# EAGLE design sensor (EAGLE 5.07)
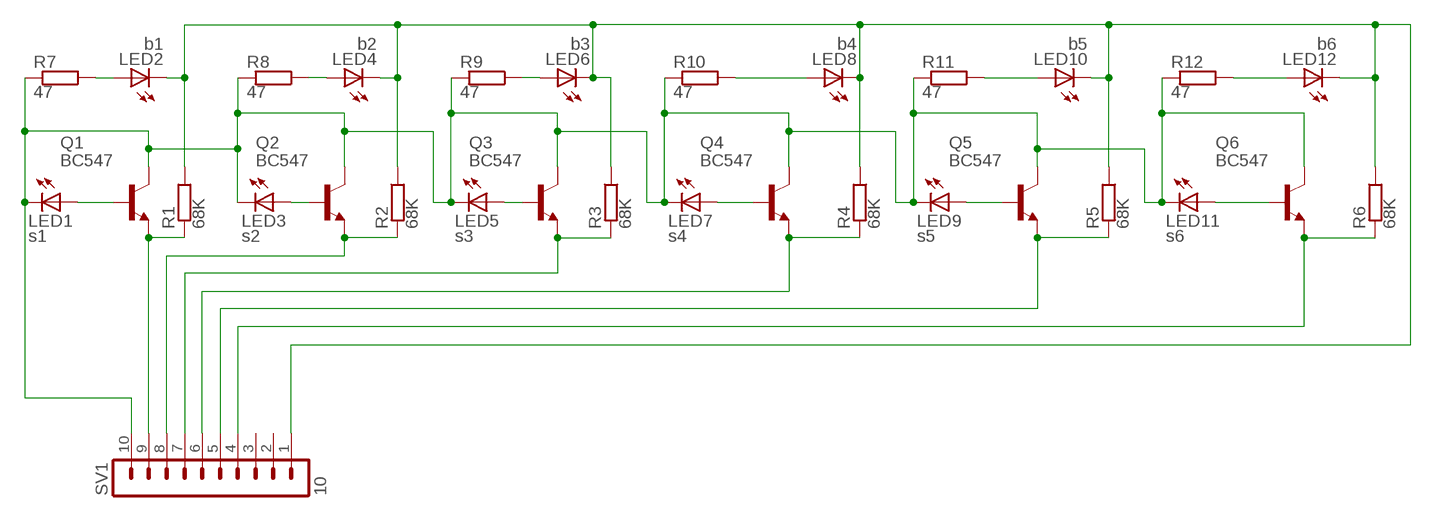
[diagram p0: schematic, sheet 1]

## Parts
LED1  s1  LED5MM  [LED5MM]
LED2  b1  LED5MM  [LED5MM]
LED3  s2  LED5MM  [LED5MM]
LED4  b2  LED5MM  [LED5MM]
LED5  s3  LED5MM  [LED5MM]
LED6  b3  LED5MM  [LED5MM]
LED7  s4  LED5MM  [LED5MM]
LED8  b4  LED5MM  [LED5MM]
LED9  s5  LED5MM  [LED5MM]
LED10  b5  LED5MM  [LED5MM]
LED11  s6  LED5MM  [LED5MM]
LED12  b6  LED5MM  [LED5MM]
Q1  BC547  [TO92]
Q2  BC547  [TO92]
Q3  BC547  [TO92]
Q4  BC547  [TO92]
Q5  BC547  [TO92]
Q6  BC547  [TO92]
R1  68K  SMK  [SMK]
R2  68K  SMK  [SMK]
R3  68K  SMK  [SMK]
R4  68K  SMK  [SMK]
R5  68K  SMK  [SMK]
R6  68K  SMK  [SMK]
R7  47  SMK  [SMK]
R8  47  SMK  [SMK]
R9  47  SMK  [SMK]
R10  47  SMK  [SMK]
R11  47  SMK  [SMK]
R12  47  SMK  [SMK]
SV1  10  MA10-1  [MA10-1]

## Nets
GRO: LED2.K(C) LED4.K(C) LED6.K(C) LED8.K(C) LED10.K(C) LED12.K(C) R1.1 R2.1 R3.1 R4.1 R5.1 R6.1 SV1.1
N$1: LED2.A R7.1
N$2: LED1.A Q1.2(B)
N$3: Q1.1(E) R1.2 SV1.9
N$4: LED4.A R8.1
N$5: LED6.A R9.1
N$6: LED3.A Q2.2(B)
N$7: Q2.1(E) R2.2 SV1.8
N$8: LED8.A R10.1
N$9: LED10.A R11.1
N$10: Q3.1(E) R3.2 SV1.7
N$11: LED5.A Q3.2(B)
N$12: LED12.A R12.1
N$14: LED9.A Q5.2(B)
N$17: Q5.1(E) R5.2 SV1.5
N$18: LED7.A Q4.2(B)
N$21: Q4.1(E) R4.2 SV1.6
N$23: LED11.A Q6.2(B)
N$24: Q6.1(E) R6.2 SV1.4
VCC: LED1.K(C) LED3.K(C) LED5.K(C) LED7.K(C) LED9.K(C) LED11.K(C) Q1.3(C) Q2.3(C) Q3.3(C) Q4.3(C) Q5.3(C) Q6.3(C) R7.2 R8.2 R9.2 R10.2 R11.2 R12.2 SV1.10
Unconnected: SV1.2 SV1.3

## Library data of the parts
LED1-LED12 = led:LED: LED
Q1-Q6 = transistor-npn:BC547*: NPN Transistor
R1-R12 = resistor-shunt:SMK: SMD SHUNT RESISTOR
SV1 = con-lstb:MA10-1: PIN HEADER

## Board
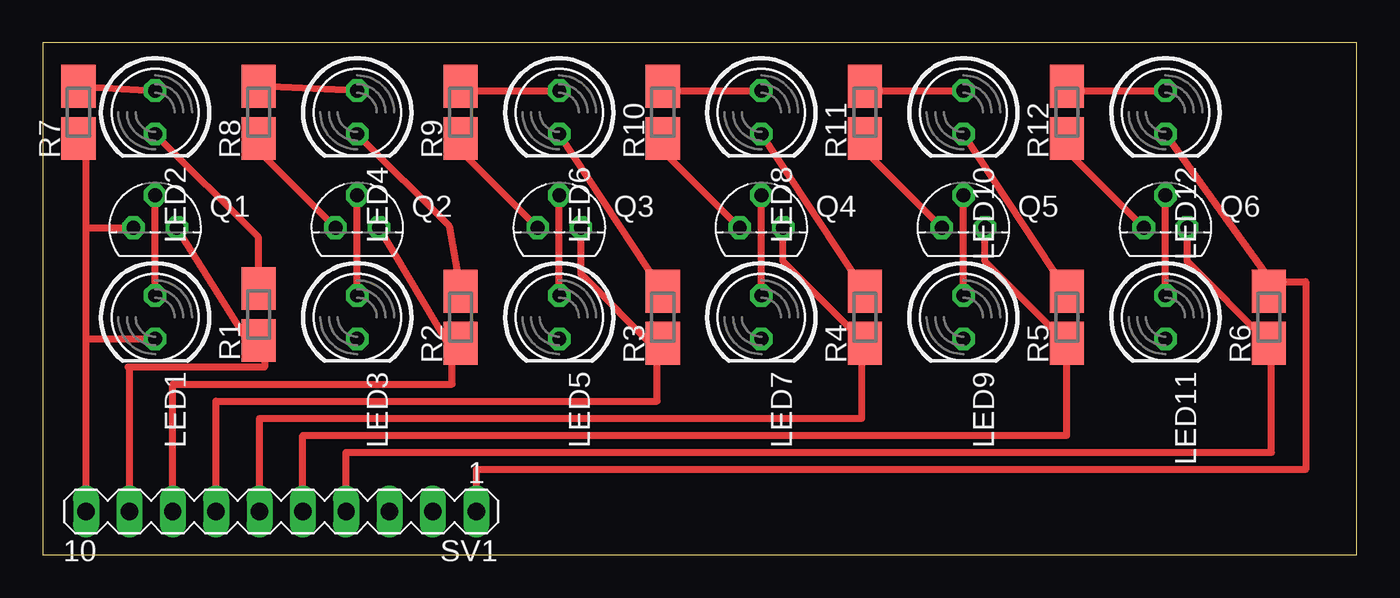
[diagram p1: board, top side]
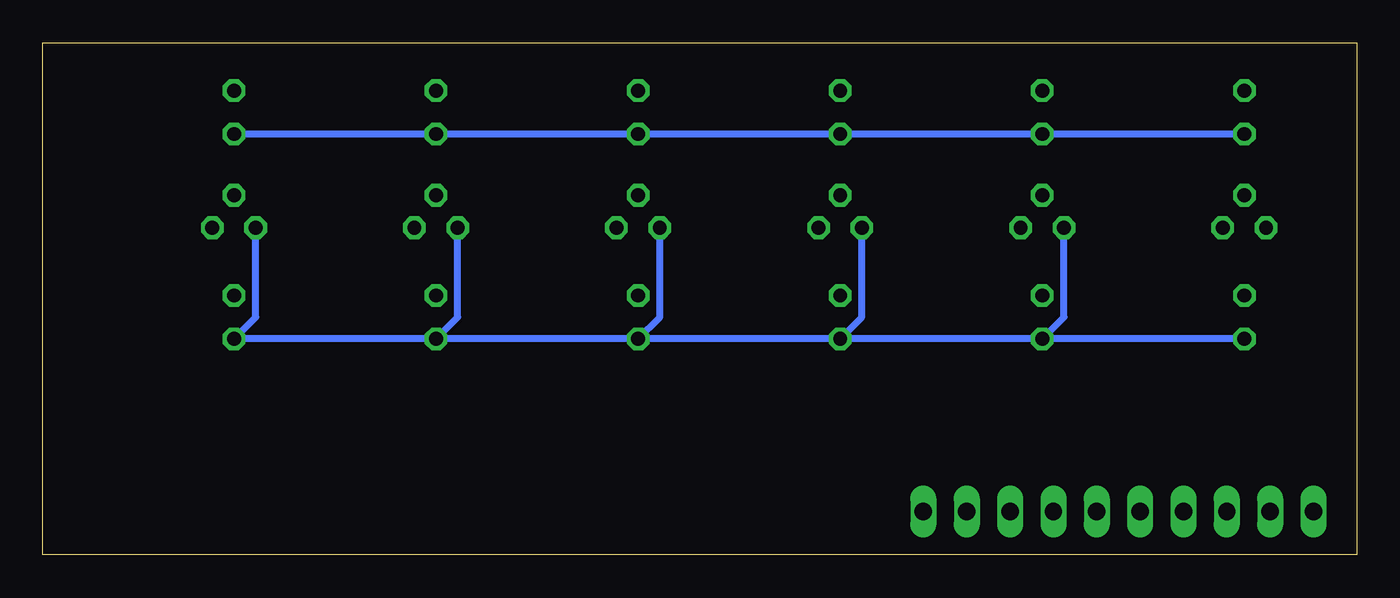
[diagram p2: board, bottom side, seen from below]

Size 77 x 30 mm. Coordinates in mm from the lower left corner, seen from the top.
Outline: 0,0 77,0 77,30 0,30 0,0
Copper layers (1*16): Top 0.035mm / dielectric 1.5mm / Bottom 0.035mm
Design rules "default": minimum track width 10mil, minimum drill 24mil, track to track 8mil, track to pad 8mil, pad to pad 8mil, via to via 8mil, smd to smd 8mil, copper to edge 40mil, drill to drill 8mil, minimum pad ring 10mil, minimum via ring 8mil, stop-mask expansion 4mil, vias tented up to drill 0mil, thermal gap 10mil

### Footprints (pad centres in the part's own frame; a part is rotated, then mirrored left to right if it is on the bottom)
LED5MM = drill 0.813 octagon: A -1.27,0; K 1.27,0
TO92 = drill 0.813 octagon: 1 1.27,0; 2 0,1.905; 3 -1.27,0
SMK = smd 2.5 x 2: 1 1.524,0; 2 -1.524,0
MA10-1 = drill 1.016 long: 1 -11.43,0; 2 -8.89,0; 3 -6.35,0; 4 -3.81,0; 5 -1.27,0; 6 1.27,0; 7 3.81,0; 8 6.35,0; 9 8.89,0; 10 11.43,0

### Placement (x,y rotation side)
LED1  6.59,13.92 270 top
LED2  6.59,25.92 270 top
LED3  18.43,13.92 270 top
LED4  18.43,25.92 270 top
LED5  30.27,13.92 270 top
LED6  30.27,25.92 270 top
LED7  42.11,13.92 270 top
LED8  42.11,25.92 270 top
LED9  53.95,13.92 270 top
LED10  53.95,25.92 270 top
LED11  65.79,13.92 270 top
LED12  65.79,25.92 270 top
Q1  6.59,19.16 0 top
Q2  18.43,19.16 0 top
Q3  30.27,19.16 0 top
Q4  42.11,19.16 0 top
Q5  53.95,19.16 0 top
Q6  65.79,19.16 0 top
R1  12.65,14.08 90 top
R2  24.49,13.92 90 top
R3  36.33,13.92 90 top
R4  48.17,13.92 90 top
R5  60.01,13.92 90 top
R6  71.85,13.92 90 top
R7  2.1,25.92 90 top
R8  12.65,25.92 90 top
R9  24.49,25.92 90 top
R10  36.33,25.92 90 top
R11  48.17,25.92 90 top
R12  60.01,25.92 90 top
SV1  13.97,2.54 180 top

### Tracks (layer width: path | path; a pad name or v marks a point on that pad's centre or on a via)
GRO
  Top 0.406: LED2.K 12.65,18.59 R1.1 | LED4.K 23.81,19.27 R2.1 | LED12.K 72,16 | 72,16 R6.1 | LED10.K R5.1 | LED8.K R4.1 | LED6.K R3.1 | SV1.1 25.4,5 74,5 74,16 72,16
  Bottom 0.406: LED2.K LED4.K LED6.K LED8.K LED10.K LED12.K
N$1
  Top 0.406: R7.1 LED2.A
N$2
  Top 0.406: LED1.A Q1.2
N$3
  Top 0.406: Q1.1 12,12.56 R1.2 13,12.56 13,11 5.08,11 | 5,11 5.08,11 | 5.08,11 SV1.9
N$4
  Top 0.406: LED4.A R8.1
N$5
  Top 0.406: LED6.A 24.49,27.19 R9.1
N$6
  Top 0.406: LED3.A Q2.2
N$7
  Top 0.406: R2.2 24,12.4 24,12 | 24,12 24,10 7.62,10 SV1.8 | 24,12 Q2.1
N$8
  Top 0.406: LED8.A 36.33,27.19 R10.1
N$9
  Top 0.406: LED10.A 48.17,27.19 R11.1
N$10
  Top 0.406: R3.2 36,12.4 36,12 | 36,12 36,9 10.16,9 SV1.7 | Q3.1 31.54,16.46 36,12
N$11
  Top 0.406: LED5.A Q3.2
N$12
  Top 0.406: LED12.A 60.01,27.19 R12.1
N$14
  Top 0.406: LED9.A Q5.2
N$17
  Top 0.406: Q5.1 55.22,17.19 R5.2 60,7 15.24,7 SV1.5
N$18
  Top 0.406: LED7.A Q4.2
N$21
  Top 0.406: SV1.6 12.7,8 48,8 48,12.4 R4.2 43.38,17.19 Q4.1
N$23
  Top 0.406: LED11.A Q6.2
N$24
  Top 0.406: SV1.4 17.78,6 72,6 72,12.4 R6.2 67.06,17.19 Q6.1
VCC
  Top 0.406: R7.2 2.54,24.4 2.54,19.16 | SV1.10 2.54,12.65 | 2.54,12.65 LED1.K | 2.54,19.16 Q1.3 | 2.54,12.65 2.54,19.16 | Q2.3 12.65,23.67 R8.2 | R9.2 24.49,23.67 Q3.3 | R10.2 36.33,23.67 Q4.3 | R11.2 48.17,23.67 Q5.3 | R12.2 60.01,23.67 Q6.3
  Bottom 0.406: LED1.K LED3.K | LED3.K 17.16,13.92 Q2.3 | LED3.K LED5.K | LED5.K LED7.K | LED7.K LED9.K | Q3.3 29,13.92 LED5.K | Q4.3 40.84,13.92 LED7.K | LED9.K LED11.K 64.52,13.92 Q6.3 | LED9.K 52.68,13.92 Q5.3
